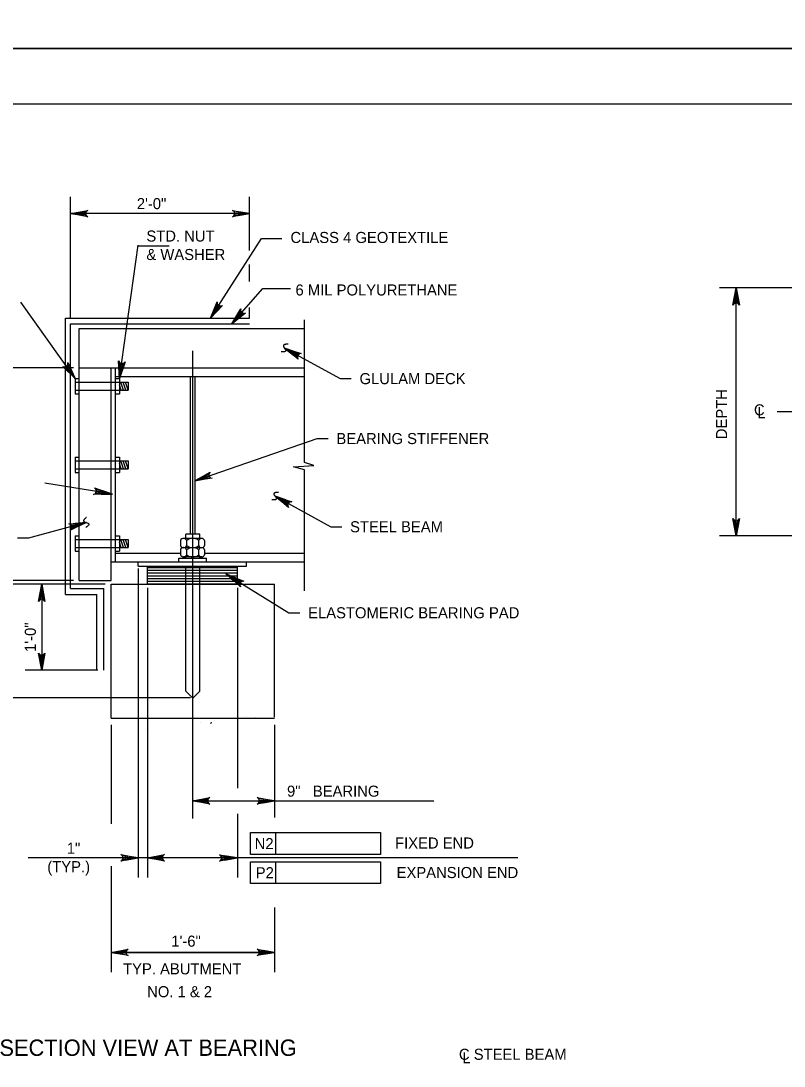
# Model space of a CAD drawing. Extents: x 638175 to 640495, y 294277 to 298435.
# Drawn here: x 639444.7 to 639651.7, y 297565.7 to 297849 of the extents above; entities that cross this region are included whole.
import ezdxf

# ---------------------------------------------------------------- set-up
doc = ezdxf.new("R2010")
doc.units = 0
for name, color, linetype in [('2', 7, 'Continuous'), ('3', 7, 'Continuous'), ('4', 7, 'Continuous'), ('5', 7, 'Continuous'), ('PLT-BNDY', 7, 'Continuous')]:
    doc.layers.add(name, color=color, linetype=linetype)

# ---------------------------------------------------------------- blocks, each defined once
blk = doc.blocks.new('25S')
at = {"layer": '4'}
blk.add_open_spline([(-1.68325, 0.611625), (-0.867125, -1.69875), (0.901125, 1.69875), (1.58125, -0.611625)], degree=2, dxfattribs=at)

msp = doc.modelspace()

# ---------------------------------------------------------------- linework, layer by layer
at = {"layer": '2'}
msp.add_line((639316.46, 297826.46), (640102.46, 297826.46), dxfattribs=at)
for points in [[(639638.66, 297776.59), (639639.53, 297771.93), (639639.28, 297772.29), (639638.97, 297772.47), (639638.66, 297772.53), (639638.34, 297772.47), (639638.03, 297772.29), (639637.78, 297771.93), (639638.66, 297776.59), (639638.03, 297772.29), (639638.34, 297772.47), (639638.66, 297776.59), (639638.66, 297772.53), (639638.97, 297772.47), (639638.66, 297776.59), (639639.28, 297772.29)], [(639638.66, 297709.44), (639637.78, 297714.1), (639638.03, 297713.75), (639638.34, 297713.56), (639638.66, 297713.51), (639638.97, 297713.56), (639639.28, 297713.75), (639639.53, 297714.1), (639638.66, 297709.44), (639639.28, 297713.75), (639638.97, 297713.56), (639638.66, 297709.44), (639638.66, 297713.51), (639638.34, 297713.56), (639638.66, 297709.44), (639638.03, 297713.75)]]:
    msp.add_lwpolyline(points, dxfattribs=at)
at = {"layer": '3'}
for p, q in [((639458.16, 297768.41), (639458.16, 297801.24)), ((639506.68, 297786.77), (639506.68, 297801.24)), ((639506.68, 297796.74), (639458.16, 297796.74)), ((639476.43, 297788.02), (639484.85, 297788.02)), ((639509.93, 297790), (639515.45, 297790)), ((639506.68, 297778.29), (639506.68, 297782.94)), ((639700.02, 297776.59), (639634.16, 297776.59)), ((639638.66, 297709.44), (639638.66, 297776.59)), ((639510.31, 297776.44), (639517.8, 297776.44)), ((639506.68, 297768.41), (639506.68, 297771.32)), ((639521.58, 297729.32), (639521.62, 297767.95)), ((639516.18, 297760.27), (639531.26, 297752.02)), ((639458.95, 297754.9), (639386.86, 297754.9)), ((639531.26, 297752.02), (639534.26, 297752.02)), ((639668.59, 297743.02), (639649.76, 297743.02)), ((639491.86, 297724.35), (639524.99, 297735.77)), ((639524.99, 297735.77), (639527.99, 297735.77)), ((639518.57, 297728.15), (639524.09, 297728.46)), ((639524.09, 297728.46), (639521.58, 297729.32)), ((639521.58, 297727.28), (639518.57, 297728.15)), ((639521.62, 297694.48), (639521.58, 297727.28)), ((639469.13, 297720.75), (639451.19, 297723.7)), ((639513.61, 297720.13), (639528.69, 297711.87)), ((639462.41, 297713.02), (639446.73, 297708.74)), ((639528.69, 297711.87), (639531.69, 297711.87)), ((639446.73, 297708.74), (639443.73, 297708.74)), ((639700.02, 297709.44), (639634.16, 297709.44)), ((639476.5, 297700.52), (639476.5, 297616.82)), ((639458.95, 297697.28), (639386.86, 297697.28)), ((639500.68, 297698.8), (639517.31, 297688.55)), ((639467.56, 297696.29), (639386.86, 297696.29)), ((639458.95, 297696.29), (639416.03, 297696.29)), ((639453.66, 297696.29), (639445.81, 297696.29)), ((639450.88, 297696.29), (639445.81, 297696.29)), ((639450.31, 297696.29), (639450.31, 297672.98)), ((639478.96, 297695.3), (639478.96, 297616.82)), ((639503.43, 297695.3), (639503.43, 297640.98)), ((639450.31, 297693.29), (639450.31, 297675.98)), ((639517.31, 297688.55), (639520.31, 297688.55)), ((639465.56, 297672.98), (639445.81, 297672.98)), ((639450.88, 297672.98), (639445.81, 297672.98)), ((639490.64, 297665.48), (639416.03, 297665.48)), ((639469.13, 297658.16), (639469.13, 297631.36)), ((639513.42, 297658.16), (639513.42, 297634.23)), ((639491.27, 297639.14), (639491.27, 297642.07)), ((639491.27, 297637.57), (639520.51, 297637.57)), ((639494.27, 297637.57), (639510.42, 297637.57)), ((639513.42, 297636.01), (639513.42, 297633.07)), ((639520.51, 297637.57), (639556.63, 297637.57)), ((639503.43, 297634.06), (639503.43, 297616.82)), ((639506.91, 297628.97), (639542.2, 297628.97)), ((639506.91, 297623.06), (639506.91, 297628.97)), ((639513.79, 297623.06), (639513.79, 297628.97)), ((639542.2, 297628.97), (639542.2, 297623.06)), ((639579.43, 297622.13), (639446.66, 297622.13)), ((639542.2, 297623.06), (639506.91, 297623.06)), ((639506.91, 297621.08), (639542.2, 297621.08)), ((639506.91, 297615.18), (639506.91, 297621.08)), ((639513.79, 297615.18), (639513.79, 297621.08)), ((639542.2, 297621.08), (639542.2, 297615.18)), ((639469.13, 297619.89), (639469.13, 297591.2)), ((639542.2, 297615.18), (639506.91, 297615.18)), ((639513.42, 297608.72), (639513.42, 297591.2)), ((639469.13, 297602.8), (639469.13, 297592.02)), ((639513.42, 297598.41), (639513.42, 297592.02)), ((639513.42, 297596.52), (639469.13, 297596.52)), ((639472.13, 297596.52), (639510.42, 297596.52))]:
    msp.add_line(p, q, dxfattribs=at)
for points in [[(639458.16, 297796.74), (639462.82, 297797.61), (639462.47, 297797.36), (639462.28, 297797.05), (639462.23, 297796.74), (639462.28, 297796.43), (639462.47, 297796.11), (639462.82, 297795.87), (639458.16, 297796.74), (639462.47, 297796.11), (639462.28, 297796.43), (639458.16, 297796.74), (639462.23, 297796.74), (639462.28, 297797.05), (639458.16, 297796.74), (639462.47, 297797.36)], [(639506.68, 297796.74), (639502.02, 297795.87), (639502.38, 297796.11), (639502.57, 297796.43), (639502.62, 297796.74), (639502.57, 297797.05), (639502.38, 297797.36), (639502.02, 297797.61), (639506.68, 297796.74), (639502.38, 297797.36), (639502.57, 297797.05), (639506.68, 297796.74), (639502.62, 297796.74), (639502.57, 297796.43), (639506.68, 297796.74), (639502.38, 297796.11)], [(639471.4, 297752.05), (639476.45, 297788.15)], [(639496.12, 297768.4), (639509.93, 297790)], [(639501.89, 297766.85), (639510.31, 297776.44)], [(639459.42, 297752.05), (639444.66, 297772.77)], [(639496.12, 297768.4), (639497.89, 297772.79), (639497.91, 297772.36), (639498.07, 297772.03), (639498.31, 297771.82), (639498.6, 297771.7), (639498.96, 297771.68), (639499.37, 297771.85), (639496.12, 297768.4), (639498.96, 297771.68), (639498.6, 297771.7), (639496.12, 297768.4), (639498.31, 297771.82), (639498.07, 297772.03), (639496.12, 297768.4), (639497.91, 297772.36)], [(639501.89, 297766.85), (639504.31, 297770.93), (639504.26, 297770.49), (639504.37, 297770.15), (639504.57, 297769.9), (639504.84, 297769.74), (639505.19, 297769.67), (639505.62, 297769.77), (639501.89, 297766.85), (639505.19, 297769.67), (639504.84, 297769.74), (639501.89, 297766.85), (639504.57, 297769.9), (639504.37, 297770.15), (639501.89, 297766.85), (639504.26, 297770.49)], [(639516.18, 297760.27), (639520.69, 297758.8), (639520.25, 297758.75), (639519.94, 297758.57), (639519.74, 297758.32), (639519.64, 297758.02), (639519.65, 297757.65), (639519.85, 297757.26), (639516.18, 297760.27), (639519.65, 297757.65), (639519.64, 297758.02), (639516.18, 297760.27), (639519.74, 297758.32), (639519.94, 297758.57), (639516.18, 297760.27), (639520.25, 297758.75)], [(639471.4, 297752.05), (639471.18, 297756.79), (639471.38, 297756.4), (639471.66, 297756.17), (639471.96, 297756.08), (639472.28, 297756.09), (639472.61, 297756.23), (639472.91, 297756.55), (639471.4, 297752.05), (639472.61, 297756.23), (639472.28, 297756.09), (639471.4, 297752.05), (639471.96, 297756.08), (639471.66, 297756.17), (639471.4, 297752.05), (639471.38, 297756.4)], [(639459.42, 297752.05), (639456, 297755.34), (639456.42, 297755.2), (639456.78, 297755.22), (639457.06, 297755.36), (639457.29, 297755.59), (639457.43, 297755.92), (639457.43, 297756.36), (639459.42, 297752.05), (639457.43, 297755.92), (639457.29, 297755.59), (639459.42, 297752.05), (639457.06, 297755.36), (639456.78, 297755.22), (639459.42, 297752.05), (639456.42, 297755.2)], [(639491.86, 297724.35), (639495.98, 297726.7), (639495.73, 297726.34), (639495.65, 297725.99), (639495.71, 297725.67), (639495.86, 297725.4), (639496.13, 297725.16), (639496.56, 297725.04), (639491.86, 297724.35), (639496.13, 297725.16), (639495.86, 297725.4), (639491.86, 297724.35), (639495.71, 297725.67), (639495.65, 297725.99), (639491.86, 297724.35), (639495.73, 297726.34)], [(639469.13, 297720.75), (639464.39, 297720.65), (639464.78, 297720.83), (639465.01, 297721.11), (639465.12, 297721.41), (639465.12, 297721.73), (639464.98, 297722.07), (639464.67, 297722.37), (639469.13, 297720.75), (639464.98, 297722.07), (639465.12, 297721.73), (639469.13, 297720.75), (639465.12, 297721.41), (639465.01, 297721.11), (639469.13, 297720.75), (639464.78, 297720.83)], [(639513.61, 297720.13), (639518.11, 297718.66), (639517.68, 297718.61), (639517.37, 297718.43), (639517.17, 297718.18), (639517.07, 297717.88), (639517.08, 297717.51), (639517.27, 297717.12), (639513.61, 297720.13), (639517.08, 297717.51), (639517.07, 297717.88), (639513.61, 297720.13), (639517.17, 297718.18), (639517.37, 297718.43), (639513.61, 297720.13), (639517.68, 297718.61)], [(639462.41, 297713.02), (639458.14, 297710.95), (639458.43, 297711.28), (639458.52, 297711.63), (639458.49, 297711.95), (639458.36, 297712.24), (639458.1, 297712.49), (639457.68, 297712.64), (639462.41, 297713.02), (639458.1, 297712.49), (639458.36, 297712.24), (639462.41, 297713.02), (639458.49, 297711.95), (639458.52, 297711.63), (639462.41, 297713.02), (639458.43, 297711.28)], [(639500.68, 297698.8), (639505.1, 297697.1), (639504.67, 297697.07), (639504.34, 297696.91), (639504.13, 297696.67), (639504.02, 297696.37), (639504.01, 297696.01), (639504.18, 297695.61), (639500.68, 297698.8), (639504.01, 297696.01), (639504.02, 297696.37), (639500.68, 297698.8), (639504.13, 297696.67), (639504.34, 297696.91), (639500.68, 297698.8), (639504.67, 297697.07)], [(639450.31, 297696.29), (639451.18, 297691.63), (639450.93, 297691.99), (639450.62, 297692.18), (639450.31, 297692.23), (639449.99, 297692.18), (639449.68, 297691.99), (639449.43, 297691.63), (639450.31, 297696.29), (639449.68, 297691.99), (639449.99, 297692.18), (639450.31, 297696.29), (639450.31, 297692.23), (639450.62, 297692.18), (639450.31, 297696.29), (639450.93, 297691.99)], [(639450.31, 297672.98), (639449.43, 297677.64), (639449.68, 297677.28), (639449.99, 297677.09), (639450.31, 297677.04), (639450.62, 297677.09), (639450.93, 297677.28), (639451.18, 297677.64), (639450.31, 297672.98), (639450.93, 297677.28), (639450.62, 297677.09), (639450.31, 297672.98), (639450.31, 297677.04), (639449.99, 297677.09), (639450.31, 297672.98), (639449.68, 297677.28)], [(639491.27, 297637.57), (639495.93, 297638.45), (639495.57, 297638.2), (639495.39, 297637.89), (639495.33, 297637.57), (639495.39, 297637.26), (639495.57, 297636.95), (639495.93, 297636.7), (639491.27, 297637.57), (639495.57, 297636.95), (639495.39, 297637.26), (639491.27, 297637.57), (639495.33, 297637.57), (639495.39, 297637.89), (639491.27, 297637.57), (639495.57, 297638.2)], [(639513.42, 297637.57), (639508.76, 297636.7), (639509.12, 297636.95), (639509.3, 297637.26), (639509.36, 297637.57), (639509.3, 297637.89), (639509.12, 297638.2), (639508.76, 297638.45), (639513.42, 297637.57), (639509.12, 297638.2), (639509.3, 297637.89), (639513.42, 297637.57), (639509.36, 297637.57), (639509.3, 297637.26), (639513.42, 297637.57), (639509.12, 297636.95)], [(639476.44, 297622.12), (639471.78, 297621.25), (639472.13, 297621.5), (639472.32, 297621.81), (639472.37, 297622.12), (639472.32, 297622.43), (639472.13, 297622.75), (639471.78, 297623), (639476.44, 297622.12), (639472.13, 297622.75), (639472.32, 297622.43), (639476.44, 297622.12), (639472.37, 297622.12), (639472.32, 297621.81), (639476.44, 297622.12), (639472.13, 297621.5)], [(639478.96, 297622.13), (639483.62, 297623.01), (639483.27, 297622.76), (639483.08, 297622.45), (639483.03, 297622.13), (639483.08, 297621.82), (639483.27, 297621.51), (639483.62, 297621.26), (639478.96, 297622.13), (639483.27, 297621.51), (639483.08, 297621.82), (639478.96, 297622.13), (639483.03, 297622.13), (639483.08, 297622.45), (639478.96, 297622.13), (639483.27, 297622.76)], [(639503.22, 297622.1), (639498.56, 297621.22), (639498.92, 297621.47), (639499.1, 297621.78), (639499.16, 297622.1), (639499.1, 297622.41), (639498.92, 297622.72), (639498.56, 297622.97), (639503.22, 297622.1), (639498.92, 297622.72), (639499.1, 297622.41), (639503.22, 297622.1), (639499.16, 297622.1), (639499.1, 297621.78), (639503.22, 297622.1), (639498.92, 297621.47)]]:
    msp.add_lwpolyline(points, dxfattribs=at)
for points in [[(639461.16, 297797.24), (639461.16, 297796.24), (639458.16, 297796.74)], [(639503.68, 297797.24), (639503.68, 297796.24), (639506.68, 297796.74)], [(639638.16, 297773.59), (639639.16, 297773.59), (639638.66, 297776.59)], [(639496.12, 297768.4), (639497.94, 297770.79), (639497.52, 297771.06)], [(639501.89, 297766.85), (639504.05, 297768.94), (639503.68, 297769.27)], [(639518.57, 297758.39), (639519.05, 297759.26), (639516.18, 297760.27)], [(639459.42, 297752.05), (639457.88, 297754.64), (639457.48, 297754.35)], [(639471.4, 297752.05), (639472.06, 297754.99), (639471.57, 297755.06)], [(639494.98, 297724.9), (639494.65, 297725.84), (639491.98, 297724.39)], [(639466.62, 297721.67), (639466.46, 297720.69), (639469.5, 297720.69)], [(639516, 297718.25), (639516.48, 297719.12), (639513.61, 297720.12)], [(639459.36, 297712.71), (639459.62, 297711.74), (639462.38, 297713.01)], [(639638.16, 297712.44), (639639.16, 297712.44), (639638.66, 297709.44)], [(639502.53, 297697.07), (639503.05, 297697.92), (639500.23, 297699.07)], [(639449.81, 297693.29), (639450.81, 297693.29), (639450.31, 297696.29)], [(639449.81, 297675.98), (639450.81, 297675.98), (639450.31, 297672.98)], [(639494.27, 297638.07), (639494.27, 297637.07), (639491.27, 297637.57)], [(639510.42, 297638.07), (639510.42, 297637.07), (639513.42, 297637.57)], [(639472.96, 297622.72), (639472.96, 297621.54), (639476.5, 297622.13)], [(639482.51, 297622.72), (639482.51, 297621.54), (639478.96, 297622.13)], [(639499.88, 297622.72), (639499.88, 297621.54), (639503.43, 297622.13)], [(639472.13, 297597.02), (639472.13, 297596.02), (639469.13, 297596.52)], [(639510.42, 297597.02), (639510.42, 297596.02), (639513.42, 297596.52)]]:
    msp.add_lwpolyline(points, close=True, dxfattribs=at)
at = {"layer": '4'}
for p, q in [((639459.42, 297752.05), (639460.51, 297752.05)), ((639459.42, 297752.05), (639459.42, 297747.89)), ((639459.42, 297751.07), (639470.31, 297751.07)), ((639470.31, 297752.05), (639471.4, 297752.05)), ((639470.31, 297751.07), (639473.72, 297751.07)), ((639471.4, 297752.05), (639471.4, 297747.89)), ((639472.48, 297748.88), (639471.78, 297751.07)), ((639473.1, 297748.88), (639472.4, 297751.07)), ((639473.72, 297748.88), (639473.02, 297751.07)), ((639473.72, 297751.07), (639473.72, 297748.88)), ((639491.86, 297752.55), (639491.86, 297709.85)), ((639459.42, 297748.88), (639470.31, 297748.88)), ((639470.31, 297748.88), (639473.72, 297748.88)), ((639471.86, 297748.88), (639471.4, 297750.32)), ((639459.42, 297747.89), (639460.51, 297747.89)), ((639470.31, 297747.89), (639471.4, 297747.89)), ((639459.42, 297730.72), (639459.42, 297726.56)), ((639459.42, 297730.72), (639460.51, 297730.72)), ((639459.42, 297729.74), (639470.31, 297729.74)), ((639470.31, 297730.72), (639471.4, 297730.72)), ((639470.31, 297729.74), (639473.72, 297729.74)), ((639471.4, 297730.72), (639471.4, 297726.56)), ((639471.86, 297727.55), (639471.4, 297728.99)), ((639472.48, 297727.55), (639471.78, 297729.74)), ((639473.1, 297727.55), (639472.4, 297729.74)), ((639473.72, 297727.55), (639473.02, 297729.74)), ((639473.72, 297729.74), (639473.72, 297727.55)), ((639459.42, 297727.55), (639470.31, 297727.55)), ((639459.42, 297726.56), (639460.51, 297726.56)), ((639470.31, 297727.55), (639473.72, 297727.55)), ((639470.31, 297726.56), (639471.4, 297726.56)), ((639459.42, 297709.4), (639460.51, 297709.4)), ((639459.42, 297709.4), (639459.42, 297705.24)), ((639470.31, 297709.4), (639471.4, 297709.4)), ((639471.4, 297709.4), (639471.4, 297705.24)), ((639459.42, 297708.41), (639470.31, 297708.41)), ((639459.42, 297706.22), (639470.31, 297706.22)), ((639470.31, 297708.41), (639473.72, 297708.41)), ((639470.31, 297706.22), (639473.72, 297706.22)), ((639471.86, 297706.22), (639471.4, 297707.66)), ((639472.48, 297706.22), (639471.78, 297708.41)), ((639473.1, 297706.22), (639472.4, 297708.41)), ((639473.72, 297706.22), (639473.02, 297708.41)), ((639473.72, 297708.41), (639473.72, 297706.22)), ((639459.42, 297705.24), (639460.51, 297705.24)), ((639470.31, 297705.24), (639471.4, 297705.24)), ((639505.78, 297660.42), (639505.78, 297660.42)), ((639513.38, 297660.82), (639513.38, 297660.82)), ((639493.38, 297658.78), (639493.38, 297658.78)), ((639496.08, 297658.58), (639496.32, 297658.86)), ((639496.36, 297658.61), (639496.32, 297658.86)), ((639497.11, 297659.28), (639497.11, 297659.28)), ((639508.41, 297660.19), (639508.41, 297660.19)), ((639478.51, 297656.83), (639478.51, 297656.83))]:
    msp.add_line(p, q, dxfattribs=at)
for points in [[(639469.13, 297596.52), (639473.79, 297597.39), (639473.43, 297597.14), (639473.24, 297596.83), (639473.19, 297596.52), (639473.24, 297596.2), (639473.43, 297595.89), (639473.79, 297595.64), (639469.13, 297596.52), (639473.43, 297595.89), (639473.24, 297596.2), (639469.13, 297596.52), (639473.19, 297596.52), (639473.24, 297596.83), (639469.13, 297596.52), (639473.43, 297597.14)], [(639513.42, 297596.52), (639508.76, 297595.64), (639509.12, 297595.89), (639509.3, 297596.2), (639509.36, 297596.52), (639509.3, 297596.83), (639509.12, 297597.14), (639508.76, 297597.39), (639513.42, 297596.52), (639509.12, 297597.14), (639509.3, 297596.83), (639513.42, 297596.52), (639509.36, 297596.52), (639509.3, 297596.2), (639513.42, 297596.52), (639509.12, 297595.89)]]:
    msp.add_lwpolyline(points, dxfattribs=at)
at = {"layer": '5'}
for p, q in [((639456.77, 297768.4), (639506.68, 297768.4)), ((639456.77, 297693.54), (639456.77, 297768.4)), ((639458.16, 297766.85), (639506.68, 297766.85)), ((639458.16, 297695.09), (639458.16, 297766.85)), ((639460.51, 297697.28), (639460.51, 297765.57)), ((639460.51, 297765.57), (639521.61, 297765.57)), ((639491.27, 297632.78), (639491.27, 297759.56)), ((639460.51, 297754.9), (639521.61, 297754.9)), ((639469.13, 297697.28), (639469.13, 297754.9)), ((639470.31, 297702.4), (639470.31, 297754.9)), ((639470.31, 297752.55), (639521.61, 297752.55)), ((639490.68, 297709.85), (639490.68, 297752.55)), ((639493.74, 297708.69), (639488.76, 297708.7)), ((639489.4, 297708.7), (639489.4, 297709.86)), ((639493.15, 297709.85), (639489.4, 297709.86)), ((639493.15, 297708.69), (639493.15, 297709.85)), ((639487.94, 297708.12), (639487.93, 297706.78)), ((639493.73, 297706.19), (639488.75, 297706.2)), ((639489.63, 297706.78), (639489.64, 297708.12)), ((639492.91, 297706.77), (639492.92, 297708.11)), ((639494.5, 297708.11), (639494.5, 297706.77)), ((639470.31, 297704.74), (639487.93, 297704.74)), ((639487.53, 297703.38), (639495.01, 297703.38)), ((639487.53, 297702.4), (639487.53, 297703.38)), ((639487.93, 297705.62), (639487.93, 297704.28)), ((639493.73, 297703.69), (639488.75, 297703.7)), ((639489.4, 297703.38), (639489.4, 297703.7)), ((639489.63, 297704.28), (639489.63, 297705.62)), ((639492.91, 297704.27), (639492.91, 297705.61)), ((639493.15, 297703.38), (639493.15, 297703.69)), ((639494.49, 297705.61), (639494.49, 297704.27)), ((639494.49, 297704.74), (639521.61, 297704.74)), ((639495.01, 297702.4), (639495.01, 297703.38)), ((639469.13, 297702.4), (639521.61, 297702.4)), ((639476.5, 297701.21), (639476.5, 297702.4)), ((639476.5, 297701.21), (639505.89, 297701.21)), ((639478.96, 297696.29), (639478.96, 297701.21)), ((639478.96, 297700.82), (639489.4, 297700.82)), ((639478.96, 297700.08), (639489.4, 297700.08)), ((639489.4, 297696.29), (639489.4, 297701.21)), ((639489.4, 297700.82), (639491.27, 297700.82)), ((639489.4, 297700.08), (639491.27, 297700.08)), ((639491.27, 297700.82), (639493.15, 297700.82)), ((639491.27, 297700.08), (639493.15, 297700.08)), ((639493.15, 297696.29), (639493.15, 297701.21)), ((639493.15, 297700.82), (639503.43, 297700.82)), ((639493.15, 297700.08), (639503.43, 297700.08)), ((639503.43, 297696.29), (639503.43, 297701.21)), ((639505.89, 297701.21), (639505.89, 297702.4)), ((639460.51, 297697.28), (639469.13, 297697.28)), ((639478.96, 297699.34), (639489.4, 297699.34)), ((639478.96, 297698.6), (639489.4, 297698.6)), ((639478.96, 297697.86), (639489.4, 297697.86)), ((639489.4, 297699.34), (639491.27, 297699.34)), ((639489.4, 297698.6), (639491.27, 297698.6)), ((639489.4, 297697.86), (639491.27, 297697.86)), ((639491.27, 297699.34), (639493.15, 297699.34)), ((639491.27, 297698.6), (639493.15, 297698.6)), ((639491.27, 297697.86), (639493.15, 297697.86)), ((639493.15, 297699.34), (639503.43, 297699.34)), ((639493.15, 297698.6), (639503.43, 297698.6)), ((639493.15, 297697.86), (639503.43, 297697.86)), ((639458.16, 297695.09), (639467.12, 297695.09)), ((639467.12, 297672.98), (639467.12, 297695.09)), ((639469.13, 297660), (639469.13, 297696.29)), ((639469.13, 297696.29), (639513.42, 297696.29)), ((639478.96, 297697.13), (639489.4, 297697.13)), ((639478.96, 297696.39), (639489.4, 297696.39)), ((639489.4, 297697.13), (639491.27, 297697.13)), ((639489.4, 297696.39), (639491.27, 297696.39)), ((639489.4, 297667.34), (639489.4, 297696.29)), ((639491.27, 297697.13), (639493.15, 297697.13)), ((639491.27, 297696.39), (639493.15, 297696.39)), ((639493.15, 297697.13), (639503.43, 297697.13)), ((639493.15, 297696.39), (639503.43, 297696.39)), ((639493.15, 297667.32), (639493.15, 297696.29)), ((639513.42, 297660.26), (639513.42, 297696.29)), ((639456.77, 297693.54), (639465.26, 297693.54)), ((639465.26, 297672.98), (639465.26, 297693.54)), ((639491.28, 297665.45), (639489.4, 297667.34)), ((639491.28, 297665.45), (639493.15, 297667.32)), ((639469.13, 297660), (639513.42, 297660))]:
    msp.add_line(p, q, dxfattribs=at)
for centre, radius, start, end in [((639488.79, 297707.79), 0.912, 88.0545, 158.5946), ((639488.79, 297707.79), 0.912, 21.1685, 88.0545), ((639491.27, 297706.09), 2.61, 50.9315, 128.8315), ((639493.71, 297707.86), 0.829, 17.3333, 162.4297), ((639488.78, 297707.11), 0.912, 201.1685, 271.7086), ((639488.78, 297705.29), 0.912, 88.0545, 158.5946), ((639488.78, 297707.11), 0.912, 271.7086, 338.5946), ((639488.78, 297705.29), 0.912, 21.1685, 88.0545), ((639491.28, 297708.81), 2.61, 230.9315, 308.8315), ((639491.27, 297703.59), 2.61, 50.9315, 128.8315), ((639493.71, 297707.02), 0.829, 197.3333, 342.4297), ((639493.7, 297705.36), 0.829, 17.3333, 162.4297), ((639488.78, 297704.61), 0.912, 201.1685, 271.7086), ((639488.78, 297704.61), 0.912, 271.7086, 338.5946), ((639491.27, 297706.31), 2.61, 230.9315, 308.8315), ((639493.7, 297704.52), 0.829, 197.3333, 342.4297)]:
    msp.add_arc(centre, radius, start, end, dxfattribs=at)
at = {"layer": 'PLT-BNDY'}
for points in [[(639276.46, 298435.46), (640117.46, 298435.46), (640117.46, 297841.46), (639276.46, 297841.46)], [(639276.46, 297841.46), (640117.46, 297841.46), (640117.46, 297247.46), (639276.46, 297247.46)]]:
    msp.add_lwpolyline(points, close=True, dxfattribs=at)

# ---------------------------------------------------------------- block references
at = {"layer": '4', "yscale": 0.7874015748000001}
for p, xscale, rotation in [((639516.18, 297760.27), 0.7874015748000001, -112.31681079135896), ((639513.61, 297720.12), 0.7874015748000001, -112.31681079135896), ((639462.38, 297713.01), 0.7874015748, -74.14105771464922)]:
    msp.add_blockref('25S', p, dxfattribs=dict(at, xscale=xscale, rotation=rotation))

# ---------------------------------------------------------------- texts
at = {"layer": '3'}
for s, height, p in [('2\'-0"', 3, (639476.11, 297797.94)), ('STD. NUT', 3, (639478.7, 297789.15)), ('CLASS 4 GEOTEXTILE', 3, (639517.78, 297788.77)), ('& WASHER', 3, (639478.7, 297784.15)), ('6 MIL POLYURETHANE', 3, (639519.14, 297774.54)), ('GLULAM DECK', 3, (639536.51, 297750.51)), ('C', 3, (639643.48, 297742.05)), ('L', 3, (639644.42, 297741.28)), ('BEARING STIFFENER', 3, (639530.24, 297734.27)), ('STEEL BEAM', 3, (639533.94, 297710.37)), ('ELASTOMERIC BEARING PAD', 3, (639522.56, 297687.05)), ('9"   BEARING', 3, (639516.84, 297638.71)), ('N2', 3, (639508.07, 297624.49)), ('FIXED END', 3, (639546.14, 297624.66)), ('1"', 3, (639457.11, 297623.24)), ('(TYP.)', 3, (639451.83, 297618.24)), ('P2', 3, (639508.36, 297616.61)), ('EXPANSION END', 3, (639546.56, 297616.66)), ('1\'-6"', 3, (639485.46, 297598.06)), ('TYP. ABUTMENT', 3, (639472.37, 297590.56)), ('NO. 1 & 2', 3, (639478.9, 297584.37)), ('SECTION VIEW AT BEARING', 4.4292, (639438.84, 297568.47)), ('C STEEL BEAM', 3, (639563.47, 297567.4)), ('L', 3, (639564.41, 297566.46))]:
    msp.add_text(s, height=height, dxfattribs=at).set_placement(p)
for s, p in [('DEPTH', (639636.18, 297735.58)), ('1\'-0"', (639448.72, 297677.94))]:
    msp.add_text(s, height=3, rotation=90, dxfattribs=at).set_placement(p)

doc.saveas('drawing.dxf')
